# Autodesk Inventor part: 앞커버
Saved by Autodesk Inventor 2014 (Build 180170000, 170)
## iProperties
Created: 2026-07
Part Number: 앞커버
Material: 알루미늄 6061
Document SubType Name: Modeling
Designer: dg
Density: 2.71 g/cm^3
Appearance: 알루미늄 - 평지
Mass: 74.5694 g
Surface Area: 103.624 cm^2
Volume: 27.5164 cm^3
Author: jhkim
Creation Date: 2026-07-02
Sending System: Autodesk Inventor 2027
Preprocessor: ST-DEVELOPER v20.1
Author: dg
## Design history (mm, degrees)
node "앞커버1"
node "솔리드1"
node "기준1"
